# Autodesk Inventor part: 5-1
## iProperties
Author: Administrator
Created: 2001-02
Part Number: 5-1
Document SubType Name: Modeling
Designer: Administrator
Control State: 0
Master: False
Checked Out: False
PropertySet Name: Design Tracking Control
Shininess: 20.0
PropertySet Name: _Private Model Information
Density: 0.0
Volumn: 0.0
Area: 0.0
PropertySet Name: Model Information
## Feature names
1. Extrusion1
2. Extrusion2
3. Extrusion3
